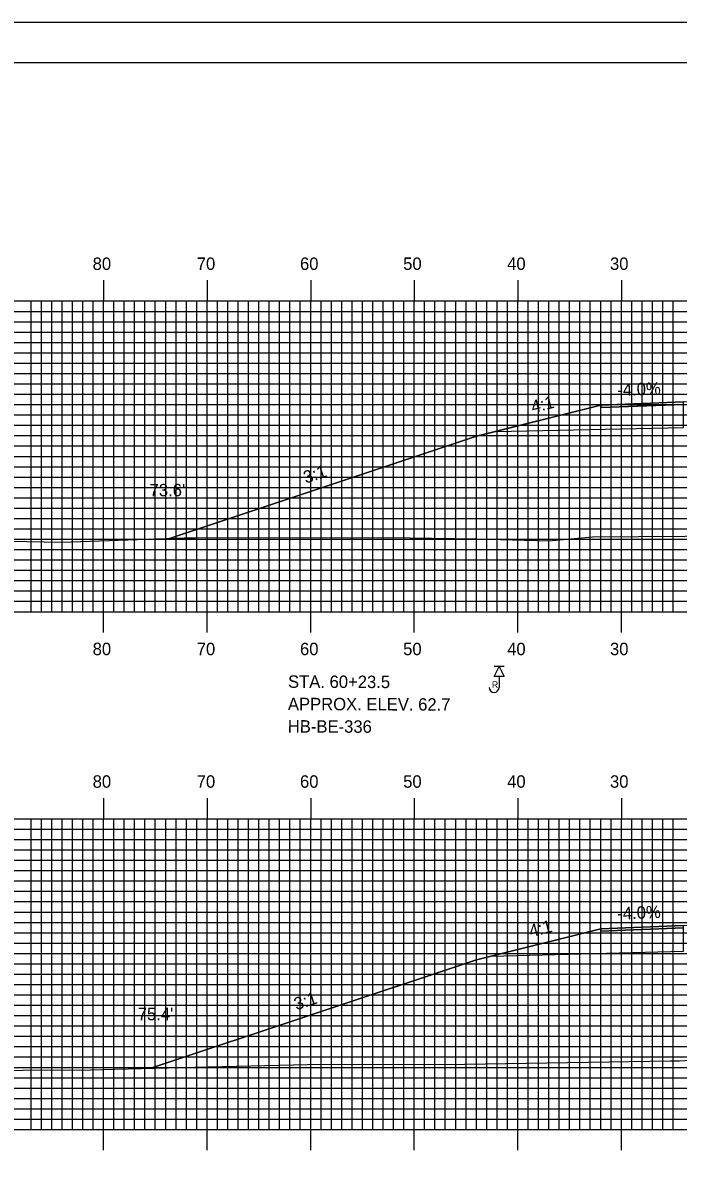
# Model space of a CAD drawing. Extents: x 1757462 to 1757806, y 442591 to 442811.
# Drawn here: x 1757540.3 to 1757603.6, y 442701.2 to 442810.5 of the extents above; entities that cross this region are included whole.
import ezdxf

# ---------------------------------------------------------------- set-up
doc = ezdxf.new("R2010")
doc.units = 0
for name, color, linetype in [('ANNOTATION', 7, 'Continuous'), ('BORDER', 7, 'Continuous'), ('BORING - REFUSAL', 7, 'Continuous'), ('D_Roadway_Centerline', 7, 'Continuous'), ('D_Roadway_Edge_Shoulder', 7, 'Continuous'), ('D_Roadway_SlopeLines', 7, 'Continuous'), ('D_Roadway_SubGrade', 7, 'Continuous'), ('D_Text_Standard', 7, 'Continuous'), ('H_V ANNOTATION', 7, 'Continuous'), ('MAJOR', 7, 'Continuous'), ('MINOR', 7, 'Continuous'), ('PLOT BOUNDARY', 7, 'Continuous'), ('S_Roadway_Centerline', 7, 'Continuous')]:
    doc.layers.add(name, color=color, linetype=linetype)

msp = doc.modelspace()

# ---------------------------------------------------------------- linework, layer by layer
at = {"layer": 'BORDER'}
msp.add_lwpolyline([(1757478.51, 442596.67), (1757798.51, 442596.67), (1757798.51, 442806.67), (1757478.51, 442806.67)], close=True, dxfattribs=at)
at = {"layer": 'BORING - REFUSAL'}
for p, q in [((1757586.79, 442748.38), (1757585.83, 442748.38)), ((1757586.31, 442747.42), (1757586.31, 442746.36))]:
    msp.add_line(p, q, dxfattribs=at)
msp.add_lwpolyline([(1757586.31, 442748.38), (1757586.79, 442747.42), (1757585.83, 442747.42)], close=True, dxfattribs=at)
msp.add_arc((1757585.82, 442746.36), 0.485, 180, 0, dxfattribs=at)
at = {"layer": 'D_Roadway_Centerline'}
for points in [[(1757554.49, 442760.74), (1757584.11, 442770.62), (1757585.94, 442771.07), (1757596.11, 442773.62), (1757604.11, 442773.94), (1757616.11, 442774.18), (1757628.11, 442774.42), (1757640.11, 442774.18), (1757648.11, 442773.86), (1757658.28, 442771.31), (1757660.11, 442770.86), (1757687.69, 442761.66)], [(1757552.67, 442709.58), (1757584.11, 442720.06), (1757585.55, 442720.42), (1757596.11, 442723.06), (1757604.11, 442723.38), (1757616.11, 442723.68), (1757628.11, 442723.92), (1757640.11, 442723.68), (1757648.11, 442723.36), (1757658.28, 442720.81), (1757660.11, 442720.36), (1757688.21, 442710.99)]]:
    msp.add_lwpolyline(points, dxfattribs=at)
at = {"layer": 'D_Roadway_Edge_Shoulder'}
for points in [[(1757604.11, 442773.94), (1757596.11, 442773.62), (1757596.11, 442773.37), (1757604.11, 442773.69)], [(1757604.11, 442723.38), (1757596.11, 442723.06), (1757596.11, 442722.81), (1757604.11, 442723.13)]]:
    msp.add_lwpolyline(points, close=True, dxfattribs=at)
at = {"layer": 'D_Roadway_SlopeLines'}
for points in [[(1757596.11, 442773.62), (1757584.11, 442770.62), (1757554.49, 442760.74)], [(1757596.11, 442723.06), (1757584.11, 442720.06), (1757552.67, 442709.58)]]:
    msp.add_lwpolyline(points, dxfattribs=at)
at = {"layer": 'D_Roadway_SubGrade'}
for points in [[(1757604.11, 442773.27), (1757604.11, 442773.69), (1757596.11, 442773.37), (1757596.11, 442773.62), (1757585.94, 442771.07), (1757604.11, 442771.44)], [(1757604.11, 442722.71), (1757604.11, 442723.13), (1757596.11, 442722.81), (1757596.11, 442723.06), (1757585.55, 442720.42), (1757604.11, 442720.88)]]:
    msp.add_lwpolyline(points, close=True, dxfattribs=at)
at = {"layer": 'MAJOR'}
for p, q in [((1757548.11, 442785.67), (1757548.11, 442783.67)), ((1757558.11, 442785.67), (1757558.11, 442783.67)), ((1757568.11, 442785.67), (1757568.11, 442783.67)), ((1757578.11, 442785.67), (1757578.11, 442783.67)), ((1757588.11, 442785.67), (1757588.11, 442783.67)), ((1757598.11, 442785.67), (1757598.11, 442783.67)), ((1757488.11, 442783.67), (1757768.11, 442783.67)), ((1757488.11, 442783.67), (1757768.11, 442783.67)), ((1757548.11, 442753.67), (1757548.11, 442783.67)), ((1757558.11, 442753.67), (1757558.11, 442783.67)), ((1757568.11, 442753.67), (1757568.11, 442783.67)), ((1757578.11, 442753.67), (1757578.11, 442783.67)), ((1757588.11, 442753.67), (1757588.11, 442783.67)), ((1757598.11, 442753.67), (1757598.11, 442783.67)), ((1757488.11, 442778.67), (1757768.11, 442778.67)), ((1757488.11, 442773.67), (1757768.11, 442773.67)), ((1757488.11, 442768.67), (1757768.11, 442768.67)), ((1757488.11, 442763.67), (1757768.11, 442763.67)), ((1757488.11, 442758.67), (1757768.11, 442758.67)), ((1757488.11, 442753.67), (1757768.11, 442753.67)), ((1757488.11, 442753.67), (1757768.11, 442753.67)), ((1757548.11, 442751.66), (1757548.11, 442753.67)), ((1757558.11, 442751.66), (1757558.11, 442753.67)), ((1757568.11, 442751.66), (1757568.11, 442753.67)), ((1757578.11, 442751.66), (1757578.11, 442753.67)), ((1757588.11, 442751.66), (1757588.11, 442753.67)), ((1757598.11, 442751.66), (1757598.11, 442753.67)), ((1757548.11, 442735.67), (1757548.11, 442733.67)), ((1757558.11, 442735.67), (1757558.11, 442733.67)), ((1757568.11, 442735.67), (1757568.11, 442733.67)), ((1757578.11, 442735.67), (1757578.11, 442733.67)), ((1757588.11, 442735.67), (1757588.11, 442733.67)), ((1757598.11, 442735.67), (1757598.11, 442733.67)), ((1757488.11, 442733.67), (1757768.11, 442733.67)), ((1757488.11, 442733.67), (1757768.11, 442733.67)), ((1757548.11, 442703.67), (1757548.11, 442733.67)), ((1757558.11, 442703.67), (1757558.11, 442733.67)), ((1757568.11, 442703.67), (1757568.11, 442733.67)), ((1757578.11, 442703.67), (1757578.11, 442733.67)), ((1757588.11, 442703.67), (1757588.11, 442733.67)), ((1757598.11, 442703.67), (1757598.11, 442733.67)), ((1757488.11, 442728.67), (1757768.11, 442728.67)), ((1757488.11, 442723.67), (1757768.11, 442723.67)), ((1757488.11, 442718.67), (1757768.11, 442718.67)), ((1757488.11, 442713.67), (1757768.11, 442713.67)), ((1757488.11, 442708.67), (1757768.11, 442708.67)), ((1757488.11, 442703.67), (1757768.11, 442703.67)), ((1757488.11, 442703.67), (1757768.11, 442703.67)), ((1757548.11, 442701.66), (1757548.11, 442703.67)), ((1757558.11, 442701.66), (1757558.11, 442703.67)), ((1757568.11, 442701.66), (1757568.11, 442703.67)), ((1757578.11, 442701.66), (1757578.11, 442703.67)), ((1757588.11, 442701.66), (1757588.11, 442703.67)), ((1757598.11, 442701.66), (1757598.11, 442703.67))]:
    msp.add_line(p, q, dxfattribs=at)
at = {"layer": 'MINOR'}
for p, q in [((1757541.11, 442753.67), (1757541.11, 442783.67)), ((1757542.11, 442753.67), (1757542.11, 442783.67)), ((1757543.11, 442753.67), (1757543.11, 442783.67)), ((1757544.11, 442753.67), (1757544.11, 442783.67)), ((1757545.11, 442753.67), (1757545.11, 442783.67)), ((1757546.11, 442753.67), (1757546.11, 442783.67)), ((1757547.11, 442753.67), (1757547.11, 442783.67)), ((1757549.11, 442753.67), (1757549.11, 442783.67)), ((1757550.11, 442753.67), (1757550.11, 442783.67)), ((1757551.11, 442753.67), (1757551.11, 442783.67)), ((1757552.11, 442753.67), (1757552.11, 442783.67)), ((1757553.11, 442753.67), (1757553.11, 442783.67)), ((1757554.11, 442753.67), (1757554.11, 442783.67)), ((1757555.11, 442753.67), (1757555.11, 442783.67)), ((1757556.11, 442753.67), (1757556.11, 442783.67)), ((1757557.11, 442753.67), (1757557.11, 442783.67)), ((1757559.11, 442753.67), (1757559.11, 442783.67)), ((1757560.11, 442753.67), (1757560.11, 442783.67)), ((1757561.11, 442753.67), (1757561.11, 442783.67)), ((1757562.11, 442753.67), (1757562.11, 442783.67)), ((1757563.11, 442753.67), (1757563.11, 442783.67)), ((1757564.11, 442753.67), (1757564.11, 442783.67)), ((1757565.11, 442753.67), (1757565.11, 442783.67)), ((1757566.11, 442753.67), (1757566.11, 442783.67)), ((1757567.11, 442753.67), (1757567.11, 442783.67)), ((1757569.11, 442753.67), (1757569.11, 442783.67)), ((1757570.11, 442753.67), (1757570.11, 442783.67)), ((1757571.11, 442753.67), (1757571.11, 442783.67)), ((1757572.11, 442753.67), (1757572.11, 442783.67)), ((1757573.11, 442753.67), (1757573.11, 442783.67)), ((1757574.11, 442753.67), (1757574.11, 442783.67)), ((1757575.11, 442753.67), (1757575.11, 442783.67)), ((1757576.11, 442753.67), (1757576.11, 442783.67)), ((1757577.11, 442753.67), (1757577.11, 442783.67)), ((1757579.11, 442753.67), (1757579.11, 442783.67)), ((1757580.11, 442753.67), (1757580.11, 442783.67)), ((1757581.11, 442753.67), (1757581.11, 442783.67)), ((1757582.11, 442753.67), (1757582.11, 442783.67)), ((1757583.11, 442753.67), (1757583.11, 442783.67)), ((1757584.11, 442753.67), (1757584.11, 442783.67)), ((1757585.11, 442753.67), (1757585.11, 442783.67)), ((1757586.11, 442753.67), (1757586.11, 442783.67)), ((1757587.11, 442753.67), (1757587.11, 442783.67)), ((1757589.11, 442753.67), (1757589.11, 442783.67)), ((1757590.11, 442753.67), (1757590.11, 442783.67)), ((1757591.11, 442753.67), (1757591.11, 442783.67)), ((1757592.11, 442753.67), (1757592.11, 442783.67)), ((1757593.11, 442753.67), (1757593.11, 442783.67)), ((1757594.11, 442753.67), (1757594.11, 442783.67)), ((1757595.11, 442753.67), (1757595.11, 442783.67)), ((1757596.11, 442753.67), (1757596.11, 442783.67)), ((1757597.11, 442753.67), (1757597.11, 442783.67)), ((1757599.11, 442753.67), (1757599.11, 442783.67)), ((1757600.11, 442753.67), (1757600.11, 442783.67)), ((1757601.11, 442753.67), (1757601.11, 442783.67)), ((1757602.11, 442753.67), (1757602.11, 442783.67)), ((1757603.11, 442753.67), (1757603.11, 442783.67)), ((1757488.11, 442782.67), (1757768.11, 442782.67)), ((1757488.11, 442781.67), (1757768.11, 442781.67)), ((1757488.11, 442780.67), (1757768.11, 442780.67)), ((1757488.11, 442779.67), (1757768.11, 442779.67)), ((1757488.11, 442777.67), (1757768.11, 442777.67)), ((1757488.11, 442776.67), (1757768.11, 442776.67)), ((1757488.11, 442775.67), (1757768.11, 442775.67)), ((1757488.11, 442774.67), (1757768.11, 442774.67)), ((1757488.11, 442772.67), (1757768.11, 442772.67)), ((1757488.11, 442771.67), (1757768.11, 442771.67)), ((1757488.11, 442770.67), (1757768.11, 442770.67)), ((1757488.11, 442769.67), (1757768.11, 442769.67)), ((1757488.11, 442767.67), (1757768.11, 442767.67)), ((1757488.11, 442766.67), (1757768.11, 442766.67)), ((1757488.11, 442765.67), (1757768.11, 442765.67)), ((1757488.11, 442764.67), (1757768.11, 442764.67)), ((1757488.11, 442762.67), (1757768.11, 442762.67)), ((1757488.11, 442761.67), (1757768.11, 442761.67)), ((1757488.11, 442760.67), (1757768.11, 442760.67)), ((1757488.11, 442759.67), (1757768.11, 442759.67)), ((1757488.11, 442757.67), (1757768.11, 442757.67)), ((1757488.11, 442756.67), (1757768.11, 442756.67)), ((1757488.11, 442755.67), (1757768.11, 442755.67)), ((1757488.11, 442754.67), (1757768.11, 442754.67)), ((1757541.11, 442703.67), (1757541.11, 442733.67)), ((1757542.11, 442703.67), (1757542.11, 442733.67)), ((1757543.11, 442703.67), (1757543.11, 442733.67)), ((1757544.11, 442703.67), (1757544.11, 442733.67)), ((1757545.11, 442703.67), (1757545.11, 442733.67)), ((1757546.11, 442703.67), (1757546.11, 442733.67)), ((1757547.11, 442703.67), (1757547.11, 442733.67)), ((1757549.11, 442703.67), (1757549.11, 442733.67)), ((1757550.11, 442703.67), (1757550.11, 442733.67)), ((1757551.11, 442703.67), (1757551.11, 442733.67)), ((1757552.11, 442703.67), (1757552.11, 442733.67)), ((1757553.11, 442703.67), (1757553.11, 442733.67)), ((1757554.11, 442703.67), (1757554.11, 442733.67)), ((1757555.11, 442703.67), (1757555.11, 442733.67)), ((1757556.11, 442703.67), (1757556.11, 442733.67)), ((1757557.11, 442703.67), (1757557.11, 442733.67)), ((1757559.11, 442703.67), (1757559.11, 442733.67)), ((1757560.11, 442703.67), (1757560.11, 442733.67)), ((1757561.11, 442703.67), (1757561.11, 442733.67)), ((1757562.11, 442703.67), (1757562.11, 442733.67)), ((1757563.11, 442703.67), (1757563.11, 442733.67)), ((1757564.11, 442703.67), (1757564.11, 442733.67)), ((1757565.11, 442703.67), (1757565.11, 442733.67)), ((1757566.11, 442703.67), (1757566.11, 442733.67)), ((1757567.11, 442703.67), (1757567.11, 442733.67)), ((1757569.11, 442703.67), (1757569.11, 442733.67)), ((1757570.11, 442703.67), (1757570.11, 442733.67)), ((1757571.11, 442703.67), (1757571.11, 442733.67)), ((1757572.11, 442703.67), (1757572.11, 442733.67)), ((1757573.11, 442703.67), (1757573.11, 442733.67)), ((1757574.11, 442703.67), (1757574.11, 442733.67)), ((1757575.11, 442703.67), (1757575.11, 442733.67)), ((1757576.11, 442703.67), (1757576.11, 442733.67)), ((1757577.11, 442703.67), (1757577.11, 442733.67)), ((1757579.11, 442703.67), (1757579.11, 442733.67)), ((1757580.11, 442703.67), (1757580.11, 442733.67)), ((1757581.11, 442703.67), (1757581.11, 442733.67)), ((1757582.11, 442703.67), (1757582.11, 442733.67)), ((1757583.11, 442703.67), (1757583.11, 442733.67)), ((1757584.11, 442703.67), (1757584.11, 442733.67)), ((1757585.11, 442703.67), (1757585.11, 442733.67)), ((1757586.11, 442703.67), (1757586.11, 442733.67)), ((1757587.11, 442703.67), (1757587.11, 442733.67)), ((1757589.11, 442703.67), (1757589.11, 442733.67)), ((1757590.11, 442703.67), (1757590.11, 442733.67)), ((1757591.11, 442703.67), (1757591.11, 442733.67)), ((1757592.11, 442703.67), (1757592.11, 442733.67)), ((1757593.11, 442703.67), (1757593.11, 442733.67)), ((1757594.11, 442703.67), (1757594.11, 442733.67)), ((1757595.11, 442703.67), (1757595.11, 442733.67)), ((1757596.11, 442703.67), (1757596.11, 442733.67)), ((1757597.11, 442703.67), (1757597.11, 442733.67)), ((1757599.11, 442703.67), (1757599.11, 442733.67)), ((1757600.11, 442703.67), (1757600.11, 442733.67)), ((1757601.11, 442703.67), (1757601.11, 442733.67)), ((1757602.11, 442703.67), (1757602.11, 442733.67)), ((1757603.11, 442703.67), (1757603.11, 442733.67)), ((1757488.11, 442732.67), (1757768.11, 442732.67)), ((1757488.11, 442731.67), (1757768.11, 442731.67)), ((1757488.11, 442730.67), (1757768.11, 442730.67)), ((1757488.11, 442729.67), (1757768.11, 442729.67)), ((1757488.11, 442727.67), (1757768.11, 442727.67)), ((1757488.11, 442726.67), (1757768.11, 442726.67)), ((1757488.11, 442725.67), (1757768.11, 442725.67)), ((1757488.11, 442724.67), (1757768.11, 442724.67)), ((1757488.11, 442722.67), (1757768.11, 442722.67)), ((1757488.11, 442721.67), (1757768.11, 442721.67)), ((1757488.11, 442720.67), (1757768.11, 442720.67)), ((1757488.11, 442719.67), (1757768.11, 442719.67)), ((1757488.11, 442717.67), (1757768.11, 442717.67)), ((1757488.11, 442716.67), (1757768.11, 442716.67)), ((1757488.11, 442715.67), (1757768.11, 442715.67)), ((1757488.11, 442714.67), (1757768.11, 442714.67)), ((1757488.11, 442712.67), (1757768.11, 442712.67)), ((1757488.11, 442711.67), (1757768.11, 442711.67)), ((1757488.11, 442710.67), (1757768.11, 442710.67)), ((1757488.11, 442709.67), (1757768.11, 442709.67)), ((1757488.11, 442707.67), (1757768.11, 442707.67)), ((1757488.11, 442706.67), (1757768.11, 442706.67)), ((1757488.11, 442705.67), (1757768.11, 442705.67)), ((1757488.11, 442704.67), (1757768.11, 442704.67))]:
    msp.add_line(p, q, dxfattribs=at)
at = {"layer": 'PLOT BOUNDARY'}
msp.add_lwpolyline([(1757462.32, 442590.55), (1757802.32, 442590.55), (1757802.32, 442810.55), (1757462.32, 442810.55)], close=True, dxfattribs=at)
at = {"layer": 'S_Roadway_Centerline'}
for points in [[(1757538.99, 442760.48), (1757544.08, 442760.38), (1757555.91, 442760.79), (1757556.18, 442760.8), (1757556.33, 442760.8), (1757556.95, 442760.8), (1757575.58, 442760.83), (1757584.08, 442760.71), (1757591.1, 442760.5), (1757595.32, 442760.89), (1757613.23, 442761.02), (1757615.91, 442761.08), (1757616.85, 442761.09), (1757639.64, 442761.23), (1757647.56, 442761.15), (1757653.65, 442761.13), (1757662.65, 442761.24), (1757672.74, 442761.41), (1757679.59, 442761.55), (1757691.61, 442761.71)], [(1757488.11, 442708.81), (1757500.51, 442708.88), (1757517.14, 442709.3), (1757522.28, 442709.3), (1757540.34, 442709.4), (1757546.84, 442709.43), (1757549.21, 442709.49), (1757558.21, 442709.71), (1757567.81, 442709.94), (1757582.95, 442709.99), (1757602.84, 442710.29), (1757603.69, 442710.3), (1757604.27, 442710.33), (1757622.81, 442710.66), (1757627.39, 442710.58), (1757634.8, 442710.66), (1757641.39, 442710.72), (1757651.4, 442710.78), (1757660.08, 442710.84), (1757662.16, 442710.84), (1757666.74, 442710.86), (1757678.09, 442711.1), (1757681.09, 442710.97), (1757696.82, 442711.01)]]:
    msp.add_lwpolyline(points, dxfattribs=at)

# ---------------------------------------------------------------- texts
at = {"layer": 'ANNOTATION'}
for s, rotation, p in [('-4.0%', 2.2906, (1757597.74, 442774.48)), ('4:1', 14.0362, (1757589.56, 442772.84)), ('3:1', 18.4348, (1757567.64, 442766.03)), ('-4.0%', 2.2906, (1757597.74, 442723.93)), ('4:1', 14.0362, (1757589.36, 442722.23)), ('3:1', 18.4348, (1757566.73, 442715.17))]:
    msp.add_text(s, height=1.2, rotation=rotation, dxfattribs=at).set_placement(p)
at = {"layer": 'BORING - REFUSAL'}
for s, p in [('STA. 60+23.5', (1757565.92, 442746.32)), ('APPROX. ELEV. 62.7', (1757565.91, 442744.16)), ('HB-BE-336', (1757565.9, 442742))]:
    msp.add_text(s, height=1.2, rotation=359.8142, dxfattribs=at).set_placement(p)
msp.add_text('R', height=0.64, dxfattribs=at).set_placement((1757585.6, 442746.3))
at = {"layer": 'D_Text_Standard'}
for s, p in [("73.6'", (1757552.56, 442764.81)), ("75.4'", (1757551.41, 442714.22))]:
    msp.add_text(s, height=1.2, dxfattribs=at).set_placement(p)
at = {"layer": 'H_V ANNOTATION'}
for s, p in [('80', (1757547.06, 442786.67)), ('70', (1757557.11, 442786.67)), ('60', (1757567.08, 442786.67)), ('50', (1757577.04, 442786.67)), ('40', (1757587.08, 442786.67)), ('30', (1757597.01, 442786.67)), ('80', (1757547.06, 442749.47)), ('70', (1757557.11, 442749.47)), ('60', (1757567.08, 442749.47)), ('50', (1757577.04, 442749.47)), ('40', (1757587.08, 442749.47)), ('30', (1757597.01, 442749.47)), ('80', (1757547.06, 442736.67)), ('70', (1757557.11, 442736.67)), ('60', (1757567.08, 442736.67)), ('50', (1757577.04, 442736.67)), ('40', (1757587.08, 442736.67)), ('30', (1757597.01, 442736.67))]:
    msp.add_text(s, height=1.2, dxfattribs=at).set_placement(p)

doc.saveas('drawing.dxf')
